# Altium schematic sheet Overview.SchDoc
size 431 x 279 mm; Date: Not shown in title block; ApprovedBy: Not shown in title block; CheckedBy: Not shown in title block; Author: Not shown in title block; CompanyName: Not shown in title block; Engineer: Not shown in title block; Organization: Not shown in title block; Address1: Not shown in title block; Address2: Not shown in title block; Address3: Not shown in title block; Address4: Not shown in title block; DocumentNumber: 1; Revision: Use project parameter SCH_Rev; SheetNumber: 2; SheetTotal: 3; PageSetup: Record=PageOptions¦CenterHorizontal=True¦CenterVertical=True¦PrintScale=1.00¦XCorrection=1.00¦YCorrection=1.00¦PrintKind=0¦BorderSize=5000000¦LeftOffset=0¦BottomOffset=0¦Orientation=2¦PaperLength=1000¦PaperWidth=1000¦Scale=100¦PaperSource=15¦PrintQuality=600¦MediaType=1¦DitherType=10¦PaperKind=Letter¦PrintScaleMode=1
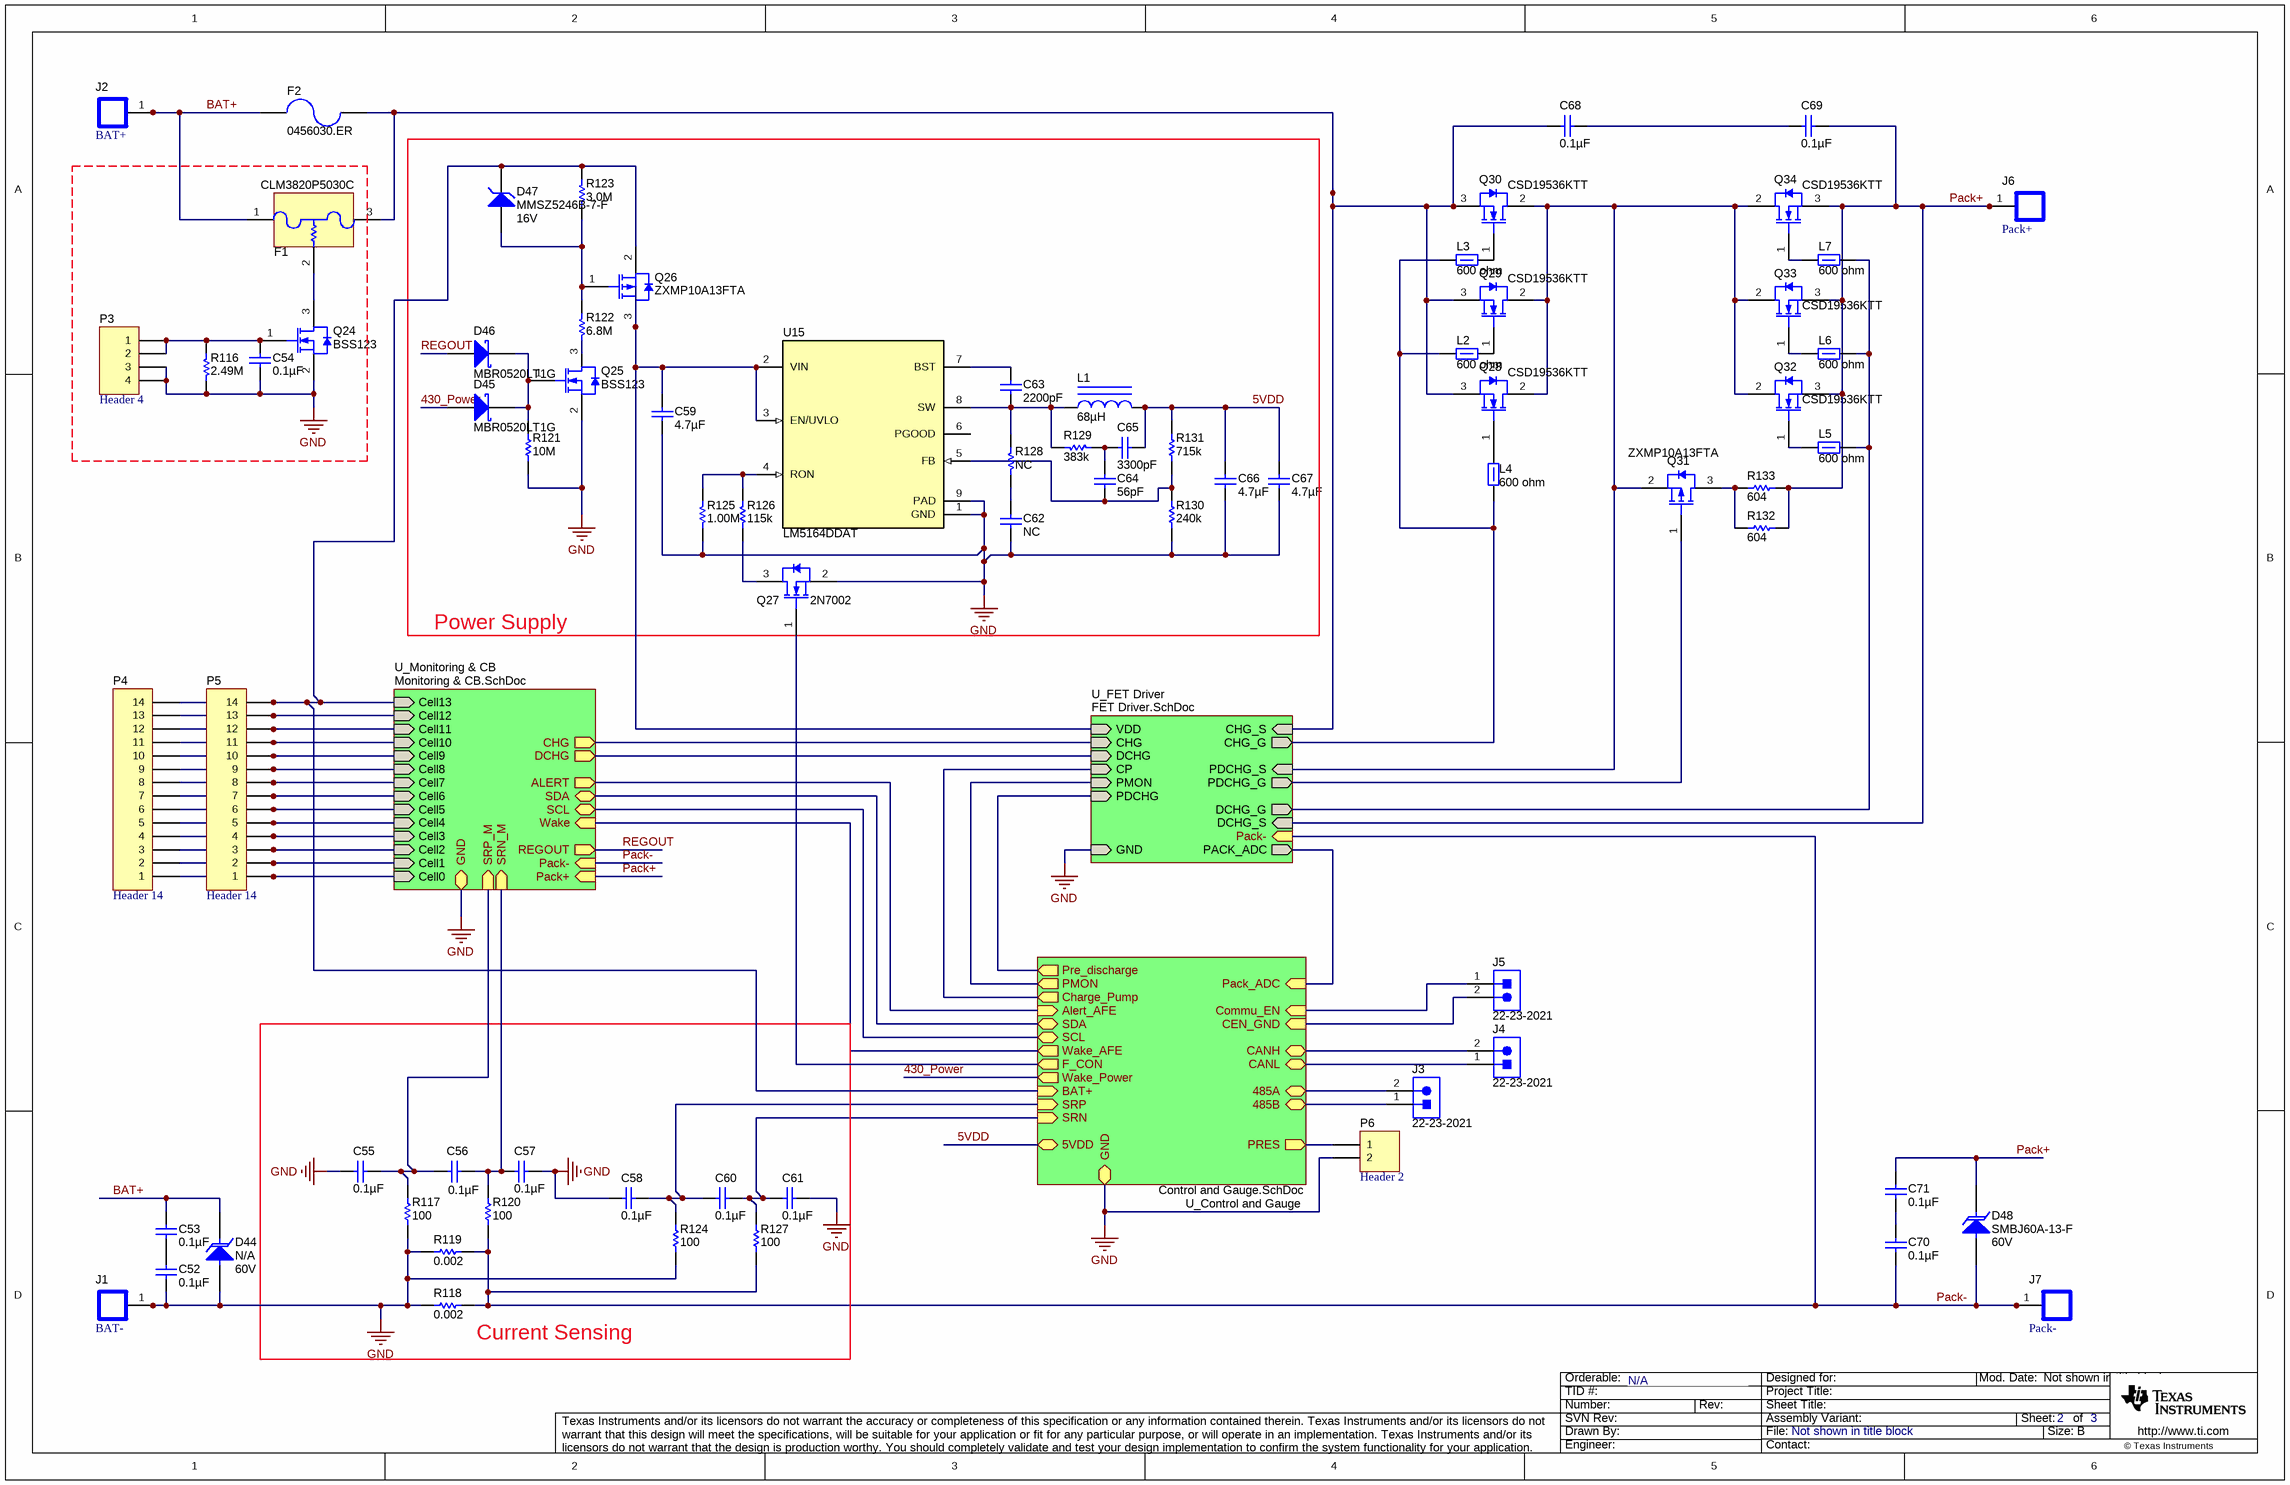
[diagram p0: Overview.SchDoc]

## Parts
C52  ValueDisplayed: 0.1µF  [0603]  (hidden comment: GRM188R72A104KA35D)
C53  ValueDisplayed: 0.1µF  [0603]  (hidden comment: GRM188R72A104KA35D)
C54  ValueDisplayed: 0.1µF  [0603]  (hidden comment: GRM188R71H104KA93D)
C55  ValueDisplayed: 0.1µF  [0603]  (hidden comment: GRM188R71H104KA93D)
C56  ValueDisplayed: 0.1µF  [0603]  (hidden comment: GRM188R71H104KA93D)
C57  ValueDisplayed: 0.1µF  [0603]  (hidden comment: GRM188R71H104KA93D)
C58  ValueDisplayed: 0.1µF  [0603]  (hidden comment: GRM188R71H104KA93D)
C59  ValueDisplayed: 4.7µF  [1210]  (hidden comment: C3225X7S2A475K200AE)
C60  ValueDisplayed: 0.1µF  [0603]  (hidden comment: GRM188R71H104KA93D)
C61  ValueDisplayed: 0.1µF  [0603]  (hidden comment: GRM188R71H104KA93D)
C62  GRM1885C1H560JA01D  [0603]  (value not drawn)
C63  ValueDisplayed: 2200pF  [0603]  (hidden comment: GRM1885C1H222JA01D)
C64  ValueDisplayed: 56pF  [0603]  (hidden comment: GRM1885C1H560JA01D)
C65  ValueDisplayed: 3300pF  [0603]  (hidden comment: GRM188R71H332KA01D)
C66  ValueDisplayed: 4.7µF  [0805_HV]  (hidden comment: GRM21BR71C475KA73L)
C67  ValueDisplayed: 4.7µF  [0805_HV]  (hidden comment: GRM21BR71C475KA73L)
C68  ValueDisplayed: 0.1µF  [0603]  (hidden comment: GRM188R72A104KA35D)
C69  ValueDisplayed: 0.1µF  [0603]  (hidden comment: GRM188R72A104KA35D)
C70  ValueDisplayed: 0.1µF  [0603]  (hidden comment: GRM188R72A104KA35D)
C71  ValueDisplayed: 0.1µF  [0603]  (hidden comment: GRM188R72A104KA35D)
D44  N/A  value 60V  [SMB]
D45  MBR0520LT1G  [SOD-123]
D46  MBR0520LT1G  [SOD-123]
D47  MMSZ5246B-7-F  value 16V  [SOD-123]
D48  SMBJ60A-13-F  value 60V  [SMB]
F1  CLM3820P5030C  [FUSE_SFK-xx30x]
F2  0456030.ER  [FUSE_0456030]
J1  BAT-  [SCREW_TERMINAL_8199]
J2  BAT+  [SCREW_TERMINAL_8199]
J3  22-23-2021  [Molex_22-23-2021]
J4  22-23-2021  [Molex_22-23-2021]
J5  22-23-2021  [Molex_22-23-2021]
J6  Pack+  [SCREW_TERMINAL_8199]
J7  Pack-  [SCREW_TERMINAL_8199]
L1  ValueDisplayed: 68µH  [WE-PD_1030]  (hidden comment: 7447713680)
L2  ValueDisplayed: 600 ohm  [0603]  (hidden comment: 74279265)
L3  ValueDisplayed: 600 ohm  [0603]  (hidden comment: 74279265)
L4  ValueDisplayed: 600 ohm  [0603]  (hidden comment: 74279265)
L5  ValueDisplayed: 600 ohm  [0603]  (hidden comment: 74279265)
L6  ValueDisplayed: 600 ohm  [0603]  (hidden comment: 74279265)
L7  ValueDisplayed: 600 ohm  [0603]  (hidden comment: 74279265)
P3  Header 4  [HDR1X4]
P4  Header 14  [HDR1X14]
P5  Header 14  [HDR1X14]
P6  Header 2  [HDR1X2]
Q24  BSS123  [SOT-23]
Q25  BSS123  [SOT-23]
Q26  ZXMP10A13FTA  [SOT-23]
Q27  2N7002  [SOT-23]
Q28  CSD19536KTT  [KTT0002A_N]
Q29  CSD19536KTT  [KTT0002A_N]
Q30  CSD19536KTT  [KTT0002A_N]
Q31  ZXMP10A13FTA  [SOT-23]
Q32  CSD19536KTT  [KTT0002A_N]
Q33  CSD19536KTT  [KTT0002A_N]
Q34  CSD19536KTT  [KTT0002A_N]
R116  ValueDisplayed: 2.49M  [0603]  (hidden comment: CRCW06032M49FKEA)
R117  ValueDisplayed: 100  [0603]  (hidden comment: CRCW0603100RFKEA)
R118  ValueDisplayed: 0.002  [2512]  (hidden comment: CSNL2512FT2L00)
R119  ValueDisplayed: 0.002  [2512]  (hidden comment: CSNL2512FT2L00)
R120  ValueDisplayed: 100  [0603]  (hidden comment: CRCW0603100RFKEA)
R121  ValueDisplayed: 10M  [0603]  (hidden comment: CRCW060310M0JNEA)
R122  ValueDisplayed: 6.8M  [0603]  (hidden comment: CRCW06036M80JNEA)
R123  ValueDisplayed: 3.0M  [0603]  (hidden comment: CRCW06033M00JNEA)
R124  ValueDisplayed: 100  [0603]  (hidden comment: CRCW0603100RFKEA)
R125  ValueDisplayed: 1.00M  [0603]  (hidden comment: CRCW06031M00FKEA)
R126  ValueDisplayed: 115k  [0603]  (hidden comment: CRCW0603115KFKEA)
R127  ValueDisplayed: 100  [0603]  (hidden comment: CRCW0603100RFKEA)
R128  RC0603FR-07383KL  [0603]  (value not drawn)
R129  ValueDisplayed: 383k  [0603]  (hidden comment: RC0603FR-07383KL)
R130  ValueDisplayed: 240k  [0603]  (hidden comment: CRCW0603240KJNEA)
R131  ValueDisplayed: 715k  [0603]  (hidden comment: CRCW0603715KFKEA)
R132  ValueDisplayed: 604  [2512]  (hidden comment: CRCW2512604RFKEG)
R133  ValueDisplayed: 604  [2512]  (hidden comment: CRCW2512604RFKEG)
U15  LM5164DDAT  [DDA0008E_N]

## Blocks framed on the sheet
Power Supply: C59 C62-C67 D45-D47 L1 Q25-Q27 R121-R123 R125 R126 R128-R131 U15
Current Sensing: C55-C58 C60 C61 R117-R120 R124 R127

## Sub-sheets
Designator = TID_Hardware.SchDoc: no entries
Designator = CoverSheet.SchDoc: no entries
U_Control and Gauge = Control and Gauge.SchDoc: SRP (in), SRN (in), BAT+ (in), Wake_Power (out), Wake_AFE (out), Alert_AFE (in), Pre_discharge (out), Charge_Pump (out), Pack_ADC (in), GND, CANH (bidir), 485B (bidir), CANL (bidir), 485A (bidir), PMON (out), SDA (bidir), SCL (bidir), Commu_EN (in), 5VDD, CEN_GND (in), PRES (out), F_CON (out)
U_FET Driver = FET Driver.SchDoc: DCHG_S (in), CHG_S (in), CHG_G (out), DCHG_G (out), PDCHG_G (out), CHG (in), CP (in), DCHG (in), PMON (in), PDCHG (in), PACK_ADC (out), VDD (in), GND (in), PDCHG_S (in), Pack- (in)
U_Monitoring & CB = Monitoring & CB.SchDoc: Cell0 (in), Cell1 (in), Cell2 (in), Cell3 (in), Cell4 (in), Cell5 (in), Cell6 (in), Cell7 (in), Cell8 (in), Cell9 (in), Cell10 (in), Cell11 (in), Cell12 (in), Cell13 (in), ALERT (out), CHG (out), DCHG (out), SDA (bidir), SCL (bidir), Pack+ (in), Pack- (in), Wake (in), REGOUT (out), GND, SRN_M (in), SRP_M (in)

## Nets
GND: C52.2 C54.2 C55.2 C57.1 C58.2 C59.2 C61.1 C62.2 C66.2 C67.2 D44.2(A) J1.1 J1.2 J1.3 J1.4 J1.5 J1.6 P3.3 P3.4 P6.2 Q24.2(S) Q25.2(S) Q27.2(S) R116.1 R117.1 R118.1 R119.1 R121.1 R124.1 R125.2 R130.1 U15.1(GND) U15.9(PAD) ; sheet U_Monitoring & CB/GND, sheet U_Control and Gauge/GND, sheet U_FET Driver/GND
5VDD: C65.2 C66.1 C67.1 L1.2 R131.2 ; sheet U_Control and Gauge/5VDD
430_Power: D45.2(A) ; sheet U_Control and Gauge/Wake_Power
BAT+: C53.1 D44.1(K) F1.1(Fuse) F2.2 J2.1 J2.2 J2.3 J2.4 J2.5 J2.6
Pack+: C69.1 C71.1 D48.1(K) J6.1 J6.2 J6.3 J6.4 J6.5 J6.6 Q32.3(S) Q33.3(S) Q34.3(S) R132.1 R133.1 ; sheet U_Monitoring & CB/Pack+, sheet U_FET Driver/DCHG_S
Pack-: C70.2 D48.2(A) J7.1 J7.2 J7.3 J7.4 J7.5 J7.6 R118.2 R119.2 R120.1 R127.1 ; sheet U_Monitoring & CB/Pack-, sheet U_FET Driver/Pack-
REGOUT: D46.2(A) ; sheet U_Monitoring & CB/REGOUT
NetC52_1: C52.1 C53.2
NetC54_1: C54.1 P3.1 P3.2 Q24.1(G) R116.2
NetC55_1: C55.1 C56.2 R117.2 ; sheet U_Monitoring & CB/SRP_M
NetC56_1: C56.1 C57.2 R120.2 ; sheet U_Monitoring & CB/SRN_M
NetC58_1: C58.1 C60.2 R124.2 ; sheet U_Control and Gauge/SRP
NetC59_1: C59.1 Q26.3(D) U15.2(VIN) U15.3(EN/UVLO) ; sheet U_FET Driver/VDD
NetC60_1: C60.1 C61.2 R127.2 ; sheet U_Control and Gauge/SRN
NetC62_1: C62.1 R128.1
NetC63_1: C63.1 U15.7(BST)
NetC63_2: C63.2 L1.1 R128.2 R129.1 U15.8(SW)
NetC64_1: C64.1 C65.1 R129.2
NetC64_2: C64.2 R130.2 R131.1 U15.5(FB)
NetC68_1: C68.1 C69.2
NetC68_2: C68.2 F1.3(Fuse) F2.1 Q28.3(S) Q29.3(S) Q30.3(S) ; sheet U_FET Driver/CHG_S
NetC70_1: C70.1 C71.2
NetD45_1: D45.1(K) D46.1(K) Q25.1(G) R121.2
NetD47_1: D47.1(K) P4.14 P5.14 Q26.2(S) R123.2 ; sheet U_Monitoring & CB/Cell13, sheet U_Control and Gauge/BAT+
NetD47_2: D47.2(A) Q26.1(G) R122.2 R123.1
NetF1_2: F1.2(Heater) Q24.3(D)
NetJ3_1: J3.1 ; sheet U_Control and Gauge/485B
NetJ3_2: J3.2 ; sheet U_Control and Gauge/485A
NetJ4_1: J4.1 ; sheet U_Control and Gauge/CANL
NetJ4_2: J4.2 ; sheet U_Control and Gauge/CANH
NetJ5_1: J5.1 ; sheet U_Control and Gauge/Commu_EN
NetJ5_2: J5.2 ; sheet U_Control and Gauge/CEN_GND
NetL2_1: L2.1 L3.1 L4.1 ; sheet U_FET Driver/CHG_G
NetL2_2: L2.2 Q29.1(G)
NetL3_2: L3.2 Q30.1(G)
NetL4_2: L4.2 Q28.1(G)
NetL5_1: L5.1 Q32.1(G)
NetL5_2: L5.2 L6.2 L7.2 ; sheet U_FET Driver/DCHG_G
NetL6_1: L6.1 Q33.1(G)
NetL7_1: L7.1 Q34.1(G)
NetP4_1: P4.1 P5.1 ; sheet U_Monitoring & CB/Cell0
NetP4_2: P4.2 P5.2 ; sheet U_Monitoring & CB/Cell1
NetP4_3: P4.3 P5.3 ; sheet U_Monitoring & CB/Cell2
NetP4_4: P4.4 P5.4 ; sheet U_Monitoring & CB/Cell3
NetP4_5: P4.5 P5.5 ; sheet U_Monitoring & CB/Cell4
NetP4_6: P4.6 P5.6 ; sheet U_Monitoring & CB/Cell5
NetP4_7: P4.7 P5.7 ; sheet U_Monitoring & CB/Cell6
NetP4_8: P4.8 P5.8 ; sheet U_Monitoring & CB/Cell7
NetP4_9: P4.9 P5.9 ; sheet U_Monitoring & CB/Cell8
NetP4_10: P4.10 P5.10 ; sheet U_Monitoring & CB/Cell9
NetP4_11: P4.11 P5.11 ; sheet U_Monitoring & CB/Cell10
NetP4_12: P4.12 P5.12 ; sheet U_Monitoring & CB/Cell11
NetP4_13: P4.13 P5.13 ; sheet U_Monitoring & CB/Cell12
NetP6_1: P6.1 ; sheet U_Control and Gauge/PRES
NetQ25_3: Q25.3(D) R122.1
NetQ27_1: Q27.1(G) ; sheet U_Control and Gauge/F_CON
NetQ27_3: Q27.3(D) R126.2
NetQ28_2: Q28.2(D) Q29.2(D) Q30.2(D) Q31.2(S) Q32.2(D) Q33.2(D) Q34.2(D) ; sheet U_FET Driver/PDCHG_S
NetQ31_1: Q31.1(G) ; sheet U_FET Driver/PDCHG_G
NetQ31_3: Q31.3(D) R132.2 R133.2
NetR125_1: R125.1 R126.1 U15.4(RON)
(unnamed): sheet U_Monitoring & CB/ALERT, sheet U_Control and Gauge/Alert_AFE
(unnamed): sheet U_Monitoring & CB/CHG, sheet U_FET Driver/CHG  [a separate net that carries the same name]
(unnamed): sheet U_Monitoring & CB/DCHG, sheet U_FET Driver/DCHG  [a separate net that carries the same name]
(unnamed): sheet U_Monitoring & CB/SDA, sheet U_Control and Gauge/SDA  [a separate net that carries the same name]
(unnamed): sheet U_Monitoring & CB/SCL, sheet U_Control and Gauge/SCL  [a separate net that carries the same name]
(unnamed): sheet U_Monitoring & CB/Wake, sheet U_Control and Gauge/Wake_AFE  [a separate net that carries the same name]
(unnamed): sheet U_Control and Gauge/Pre_discharge, sheet U_FET Driver/PDCHG  [a separate net that carries the same name]
(unnamed): sheet U_Control and Gauge/Charge_Pump, sheet U_FET Driver/CP  [a separate net that carries the same name]
(unnamed): sheet U_Control and Gauge/Pack_ADC, sheet U_FET Driver/PACK_ADC  [a separate net that carries the same name]
(unnamed): sheet U_Control and Gauge/PMON, sheet U_FET Driver/PMON  [a separate net that carries the same name]

Not connected (* = marked no-connect by the designer): U15 6(PGOOD)

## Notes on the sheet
- N/A

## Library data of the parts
C52 C53 C68-C71 = GRM188R72A104KA35D: CAP, CERM, 0.1 µF, 100 V,+/- 10%, X7R, 0603; Manufacturer: MuRata; Polarized: N; CompType: Capacitor; Value: 0.1uF; U/M: EA; Cap_F: 0.0000001; Tolerance_%: 10; VDC_V: 100; Value2: 100V; TaMin_C: -55; TaMax_C: 125; SizeArea_mm2: 1.28; SizeAreaWB_mm2: 4.68; SizeX_mm: 1.6; SizeY_mm: 0.8; SizeZ_mm: 1; AEC Category: Q200; Green_Lifecycle: Active; Green_REACh: Passed
C54-C58 C60 C61 = GRM188R71H104KA93D: CAP, CERM, 0.1 µF, 50 V,+/- 10%, X7R, 0603; Manufacturer: MuRata; Polarized: N; CompType: Capacitor; Value: 0.1uF; U/M: EA; Cap_F: 0.0000001; Tolerance_%: 10; VDC_V: 50; Value2: 50V; TaMin_C: -55; TaMax_C: 125; SizeArea_mm2: 1.28; SizeAreaWB_mm2: 4.68; SizeX_mm: 1.6; SizeY_mm: 0.8; SizeZ_mm: 1; AEC Category: Q200; Green_Lifecycle: Active; Green_REACh: Passed
C59 = C3225X7S2A475K200AE: CAP, CERM, 4.7 µF, 100 V,+/- 10%, X7S, 1210; Manufacturer: TDK; Polarized: N; CompType: Capacitor; Value: 4.7uF; U/M: EA; Cap_F: 0.0000047; Tolerance_%: 10; VDC_V: 100; Value2: 100V; TaMin_C: -55; TaMax_C: 125; SizeArea_mm2: 8; SizeAreaWB_mm2: 14.7; SizeX_mm: 3.2; SizeY_mm: 2.5; SizeZ_mm: 1.35; AEC Category: Q200; Green_Lifecycle: Active; Green_REACh: Passed
C62 = GRM1885C1H560JA01D: NC; Manufacturer: MuRata; Polarized: N; CompType: Capacitor; Value: 56pF; U/M: EA; Cap_F: 0.000000000056; Tolerance_%: 5; VDC_V: 50; Value2: 50V; TempCo: C0G/NP0; TaMin_C: -55; TaMax_C: 125; SizeArea_mm2: 1.28; SizeAreaWB_mm2: 4.68; SizeX_mm: 1.6; SizeY_mm: 0.8; SizeZ_mm: 1; AEC Category: Q200; Green_Lifecycle: Active; Green_REACh: Passed
C63 = GRM1885C1H222JA01D: CAP, CERM, 2200 pF, 50 V,+/- 5%, C0G/NP0, 0603; Manufacturer: MuRata; Polarized: N; CompType: Capacitor; Value: 2200pF; U/M: EA; Cap_F: 0.0000000022; Tolerance_%: 5; VDC_V: 50; Value2: 50V; TaMin_C: -55; TaMax_C: 125; SizeArea_mm2: 1.28; SizeAreaWB_mm2: 4.68; SizeX_mm: 1.6; SizeY_mm: 0.8; SizeZ_mm: 1; AEC Category: Q200; Green_Lifecycle: Active; Green_REACh: Passed
C64 = GRM1885C1H560JA01D: CAP, CERM, 56 pF, 50 V,+/- 5%, C0G/NP0, 0603; Manufacturer: MuRata; Polarized: N; CompType: Capacitor; Value: 56pF; U/M: EA; Cap_F: 0.000000000056; Tolerance_%: 5; VDC_V: 50; Value2: 50V; TaMin_C: -55; TaMax_C: 125; SizeArea_mm2: 1.28; SizeAreaWB_mm2: 4.68; SizeX_mm: 1.6; SizeY_mm: 0.8; SizeZ_mm: 1; AEC Category: Q200; Green_Lifecycle: Active; Green_REACh: Passed
C65 = GRM188R71H332KA01D: CAP, CERM, 3300 pF, 50 V,+/- 10%, X7R, 0603; Manufacturer: MuRata; Polarized: N; CompType: Capacitor; Value: 3300pF; U/M: EA; Cap_F: 0.0000000033; Tolerance_%: 10; VDC_V: 50; Value2: 50V; TaMin_C: -55; TaMax_C: 125; SizeArea_mm2: 1.28; SizeAreaWB_mm2: 4.68; SizeX_mm: 1.6; SizeY_mm: 0.8; SizeZ_mm: 1; AEC Category: Q200; Green_Lifecycle: Active; Green_REACh: Passed
C66 C67 = GRM21BR71C475KA73L: CAP, CERM, 4.7 µF, 16 V,+/- 10%, X7R, 0805; Manufacturer: MuRata; Polarized: N; CompType: Capacitor; Value: 4.7uF; U/M: EA; Cap_F: 0.0000047; Tolerance_%: 10; ESR_ohm: 0.006; Value1: 0.006 ohm; VDC_V: 16; Value2: 16V; TaMin_C: -55; TaMax_C: 125; Cap_Case: 0805; SizeArea_mm2: 2.5; SizeAreaWB_mm2: 6.75; SizeX_mm: 2; SizeY_mm: 1.25; SizeZ_mm: 1.45; AEC Category: Q200; Green_Lifecycle: Active; Green_REACh: Passed
D44 D48 = SMBJ60A-13-F: Diode, TVS, Uni, 60 V, 96.8 Vc, SMB; Manufacturer: Diodes Inc.; U/M: EA; Power_W: 5; Vr_V: 60; Value1: 5W; SizeAreaWB_mm2: 44.156; SizeArea_mm2: 21.336; SizeX_mm: 5.6; SizeY_mm: 3.81; SizeZ_mm: 2.6; AEC Category: Q101
D45 D46 = MBR0520LT1G: Diode, Schottky, 20 V, 0.5 A, SOD-123; Manufacturer: ON Semiconductor; U/M: EA; Vf_V: 0.385; Value: 20V; Value1: 0.5A; Value2: 0.385V; Io_A: 0.5; Vr_V: 20; TJmax_C: 125; RJC_CperW: 150; SizeAreaWB_mm2: 13.095; SizeArea_mm2: 6.545; SizeX_mm: 3.85; SizeY_mm: 1.7; SizeZ_mm: 1.35; AEC Category: Q101; Green_Lifecycle: Active; Green_REACh: Passed
D47 = MMSZ5246B-7-F: Diode, Zener, 16 V, 500 mW, SOD-123; Manufacturer: Diodes Inc.; SymbolCreator: a0412235; U/M: EA; Power_W: 0.5; Vz_V: 16; Value1: 0.5W; RJA_CperW: 350; SizeAreaWB_mm2: 13.095; SizeArea_mm2: 6.545; SizeX_mm: 3.85; SizeY_mm: 1.7; SizeZ_mm: 1.35; AEC Category: Q101; Green_Lifecycle: Active; Green_REACh: Passed
F1 = SFK-5030: Fuse, 30 A, SMD; Manufacturer: POLYTRONICS; SymbolCreator: x0208325; VDC_V: 62; Irating_A: 30; Rtyp_Ohm: 0.0015
F2 = 0456030.ER: Fuse, 30 A, 125 VAC, 72 VDC, SMD; Manufacturer: Littelfuse; VDC_V: 72; VAC_V: 125; Irating_A: 30; Rtyp_Ohm: 0.00132; MeltingTyp: 81
J1 J2 J6 J7 = 8199: TERMINAL SCREW PC 30AMP, TH; Manufacturer: Keystone; SymbolCreator: a0799628; CompType: Screw Connector; Green_Lifecycle: Active; Green_REACh: Passed
J3-J5 = 22-23-2021: Header, 2.54mm, 2x1, Vertical, TH; Manufacturer: Molex; SymbolCreator: a0412235; Green_Lifecycle: Active; Green_REACh: Passed
L1 = 7447713680: Inductor, Shielded Drum Core, Ferrite, 68 µH, 1.1 A, 0.275 ohm, SMD; Manufacturer: Wurth Elektronik; Value: 68uH; Ind_H: 68.0E-6; Imax_A: 1.1; Irms: 1.1A @ 40C rise; Isat: 1.6A @ 10% inductance drop; DCR_ohm: 0.275; Value2: 1.1A; SizeAreaWB_mm2: 144; SizeArea_mm2: 100; SizeX_mm: 10; SizeZ_mm: 3; AEC Category: Q200; Green_Lifecycle: Active; Green_REACh: Passed
L2-L7 = 74279265: Ferrite Bead, 600 ohm @ 100 MHz, 0.2 A, 0603; Manufacturer: Wurth Elektronik; Value: 600 ohm; Imax_A: 0.2; DCR_ohm: 0.45; Value1: 0.45 ohm; Value2: 0.2A; SizeAreaWB_mm2: 4.68; SizeArea_mm2: 1.28; SizeX_mm: 1.6; SizeY_mm: 0.8; SizeZ_mm: 1; ZTyp@100MHz_Ohm: 600; Ztyp@1GHz_Ohm: 223.805; Green_Lifecycle: Active; Green_REACh: Passed
P3 = Header 4: Header, 4-Pin
P4 P5 = Header 14: Header, 14-Pin
P6 = Header 2: Header, 2-Pin
Q24 Q25 = BSS123: MOSFET, N-CH, 100 V, 0.17 A, SOT-23; Manufacturer: Fairchild Semiconductor; Alternate Manufacturer: None; U/M: EA; ChType: N; Value: 100V; VdsMax_V: 100; Value1: 10 ohm; Rdson45_ohm: 10; Value2: 1.8 nC; QgTyp_nC: 1.8; Vgs_V: 20; IdsMax_A: 0.17; SizeAreaWB_mm2: 14; SizeArea_mm2: 7.5; SizeX_mm: 2.5; SizeY_mm: 3; SizeZ_mm: 1.1; AEC Category: Q101; Green_Lifecycle: Active; Green_REACh: Passed
Q26 Q31 = ZXMP10A13FTA: MOSFET, P-CH, -100 V, -0.6 A, SOT-23; Manufacturer: Diodes Inc.; Alternate Manufacturer: None; U/M: EA; ChType: P; Value: -100V; Value1: 1 ohm; Rdson45_ohm: 1; Value2: 3.5 nC; QgTyp_nC: 3.5; Vgs_V: -4; SizeAreaWB_mm2: 14; SizeArea_mm2: 7.5; SizeX_mm: 2.5; SizeY_mm: 3; SizeZ_mm: 1.1; AEC Category: Q101; Green_Lifecycle: Active; Green_REACh: Passed
Q27 = 2N7002: MOSFET, N-CH, 60 V, 115 A, SOT-23; Manufacturer: Fairchild Semiconductor; Alternate Manufacturer: None; U/M: EA; ChType: N; Value: 60V; VdsMax_V: 60; Value1: ? ohm; Value2: ? nC; Vgs_V: 20; IdsMax_A: 115; SizeAreaWB_mm2: 14; SizeArea_mm2: 7.5; SizeX_mm: 2.5; SizeY_mm: 3; SizeZ_mm: 1.1; AEC Category: Q101; Green_Lifecycle: Active; Green_REACh: Passed
Q28-Q30 Q32-Q34 = CSD19536KTT: MOSFET, N-CH, 100 V, 200 A, KTT0002A (TO-263-2); Manufacturer: Texas Instruments; Alternate Manufacturer: None; U/M: EA; ChType: N; Value: 100V; VdsMax_V: 100; Value1: ? ohm; Value2: 118 nC; QgTyp_nC: 118; Vgs_V: 20; IdsMax_A: 200; SizeAreaWB_mm2: 198.208; SizeArea_mm2: 145.288; SizeX_mm: 14.3; SizeY_mm: 10.16; SizeZ_mm: 4.7; AEC Category: Q101
R116 = CRCW06032M49FKEA: RES, 2.49 M, 1%, 0.1 W, 0603; Manufacturer: Vishay-Dale; CompType: Resistor; Value: 2.49Meg; Res_ohm: 2490000; Value_Code: 2M49; Tolerance_%: 1; Power_W: 0.1; Value2: 0.1W; VDC_V: 75; TempCo: 100 ppm/C; SizeArea_mm2: 1.28; SizeX_mm: 1.6; SizeY_mm: 0.8; EIA_Code: E96; U/M: EA; AEC Category: Q200
R117 R120 R124 R127 = CRCW0603100RFKEA: RES, 100, 1%, 0.1 W, 0603; Manufacturer: Vishay-Dale; CompType: Resistor; Value: 100; Value_Code: 100R; Tolerance_%: 1; Power_W: 0.1; Value2: 0.1W; VDC_V: 75; TempCo: 100 ppm/C; SizeArea_mm2: 1.28; SizeX_mm: 1.6; SizeY_mm: 0.8; EIA_Code: E96; U/M: EA; AEC Category: Q200; Green_Lifecycle: Active; Green_REACh: Passed
R118 R119 = CSNL2512FT2L00: RES, 0.002, 1%, 2 W, 2512; Manufacturer: Stackpole Electronics Inc; CompType: Resistor; Value: 0.002; Value_Code: 2L000; Tolerance_%: 1; Power_W: 2; Value2: 2W; VDC_V: 200; TempCo: 50 ppm/C; SizeArea_mm2: 20.16; SizeX_mm: 6.3; SizeY_mm: 3.2; SizeZ_mm: 0.71; U/M: EA; AEC Category: Q200
R121 = CRCW060310M0JNEA: RES, 10 M, 5%, 0.1 W, 0603; Manufacturer: Vishay-Dale; CompType: Resistor; Value: 10Meg; Res_ohm: 10000000; Value_Code: 10M0; Tolerance_%: 5; Power_W: 0.1; Value2: 0.1W; VDC_V: 75; TempCo: 200 ppm/C; SizeArea_mm2: 1.28; SizeX_mm: 1.6; SizeY_mm: 0.8; SizeZ_mm: 1; EIA_Code: E24; U/M: EA; AEC Category: Q200; Green_Lifecycle: Active; Green_REACh: Passed
R122 = CRCW06036M80JNEA: RES, 6.8 M, 5%, 0.1 W, 0603; Manufacturer: Vishay-Dale; CompType: Resistor; Value: 6.8Meg; Res_ohm: 6800000; Value_Code: 6M80; Tolerance_%: 5; Power_W: 0.1; Value2: 0.1W; VDC_V: 75; TempCo: 200 ppm/C; SizeArea_mm2: 1.28; SizeX_mm: 1.6; SizeY_mm: 0.8; SizeZ_mm: 1; EIA_Code: E24; U/M: EA; AEC Category: Q200
R123 = CRCW06033M00JNEA: RES, 3.0 M, 5%, 0.1 W, 0603; Manufacturer: Vishay-Dale; CompType: Resistor; Value: 3.0Meg; Res_ohm: 3000000; Value_Code: 3M00; Tolerance_%: 5; Power_W: 0.1; Value2: 0.1W; VDC_V: 75; TempCo: 200 ppm/C; SizeArea_mm2: 1.28; SizeX_mm: 1.6; SizeY_mm: 0.8; SizeZ_mm: 1; EIA_Code: E24; U/M: EA; AEC Category: Q200; Green_Lifecycle: Active; Green_REACh: Passed
R125 = CRCW06031M00FKEA: RES, 1.00 M, 1%, 0.1 W, 0603; Manufacturer: Vishay-Dale; CompType: Resistor; Value: 1.00Meg; Res_ohm: 1000000; Value_Code: 1M00; Tolerance_%: 1; Power_W: 0.1; Value2: 0.1W; VDC_V: 75; TempCo: 100 ppm/C; SizeArea_mm2: 1.28; SizeX_mm: 1.6; SizeY_mm: 0.8; EIA_Code: E96; U/M: EA; AEC Category: Q200; Green_Lifecycle: Active; Green_REACh: Passed
R126 = CRCW0603115KFKEA: RES, 115 k, 1%, 0.1 W, 0603; Manufacturer: Vishay-Dale; CompType: Resistor; Value: 115k; Res_ohm: 115000; Tolerance_%: 1; Power_W: 0.1; Value2: 0.1W; VDC_V: 75; TempCo: 100 ppm/C; SizeArea_mm2: 1.28; SizeX_mm: 1.6; SizeY_mm: 0.8; EIA_Code: E96; U/M: EA; AEC Category: Q200; Green_Lifecycle: Active; Green_REACh: Passed
R128 = RC0603FR-07383KL: NC; Manufacturer: Yageo America; CompType: Resistor; Value: 383k; Res_ohm: 383000; Tolerance_%: 1; Value1: 1%; Power_W: 0.1; Value2: 0.1W; VDC_V: 150; TempCo: 200 ppm/C; SizeArea_mm2: 1.28; SizeX_mm: 1.6; SizeY_mm: 0.8; EIA_Code: E96; U/M: EA; AEC Category: Q200
R129 = RC0603FR-07383KL: RES, 383 k, 1%, 0.1 W, 0603; Manufacturer: Yageo America; CompType: Resistor; Value: 383k; Res_ohm: 383000; Tolerance_%: 1; Power_W: 0.1; Value2: 0.1W; VDC_V: 150; TempCo: 200 ppm/C; SizeArea_mm2: 1.28; SizeX_mm: 1.6; SizeY_mm: 0.8; EIA_Code: E96; U/M: EA; AEC Category: Q200
R130 = CRCW0603240KJNEA: RES, 240 k, 5%, 0.1 W, 0603; Manufacturer: Vishay-Dale; CompType: Resistor; Value: 240k; Res_ohm: 240000; Tolerance_%: 5; Power_W: 0.1; Value2: 0.1W; VDC_V: 75; TempCo: 200 ppm/C; SizeArea_mm2: 1.28; SizeX_mm: 1.6; SizeY_mm: 0.8; SizeZ_mm: 1; EIA_Code: E24; U/M: EA; AEC Category: Q200; Green_Lifecycle: Active; Green_REACh: Passed
R131 = CRCW0603715KFKEA: RES, 715 k, 1%, 0.1 W, 0603; Manufacturer: Vishay-Dale; CompType: Resistor; Value: 715k; Res_ohm: 715000; Tolerance_%: 1; Power_W: 0.1; Value2: 0.1W; VDC_V: 75; TempCo: 100 ppm/C; SizeArea_mm2: 1.28; SizeX_mm: 1.6; SizeY_mm: 0.8; EIA_Code: E96; U/M: EA; AEC Category: Q200
R132 R133 = CRCW2512604RFKEG: RES, 604, 1%, 1 W, AEC-Q200 Grade 0, 2512; Manufacturer: Vishay-Dale; CompType: Resistor; Value: 604; Value_Code: 604R; Tolerance_%: 1; Value2: 1W; VDC_V: 500; TempCo: 100 ppm/C; SizeArea_mm2: 20.16; SizeX_mm: 6.3; SizeY_mm: 3.2; SizeZ_mm: 0.71; EIA_Code: E96; U/M: EA; AEC Category: Q200; AEC Qualified: Y; AEC Grade: 0
U15 = CMP-0080798-1: 100-V Low IQ Synchronous Buck Regulator, DDA0008E (SOIC-8); Alternate Manufacturer: Texas Instruments; SizeAreaWB_mm2: 57.4; SizeZ_mm: 1.7; SizeX_mm: 5; SizeY_mm: 6.2; SizeArea_mm2: 31; CompType: IC; AEC Qualified: N; AEC Category: Q200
